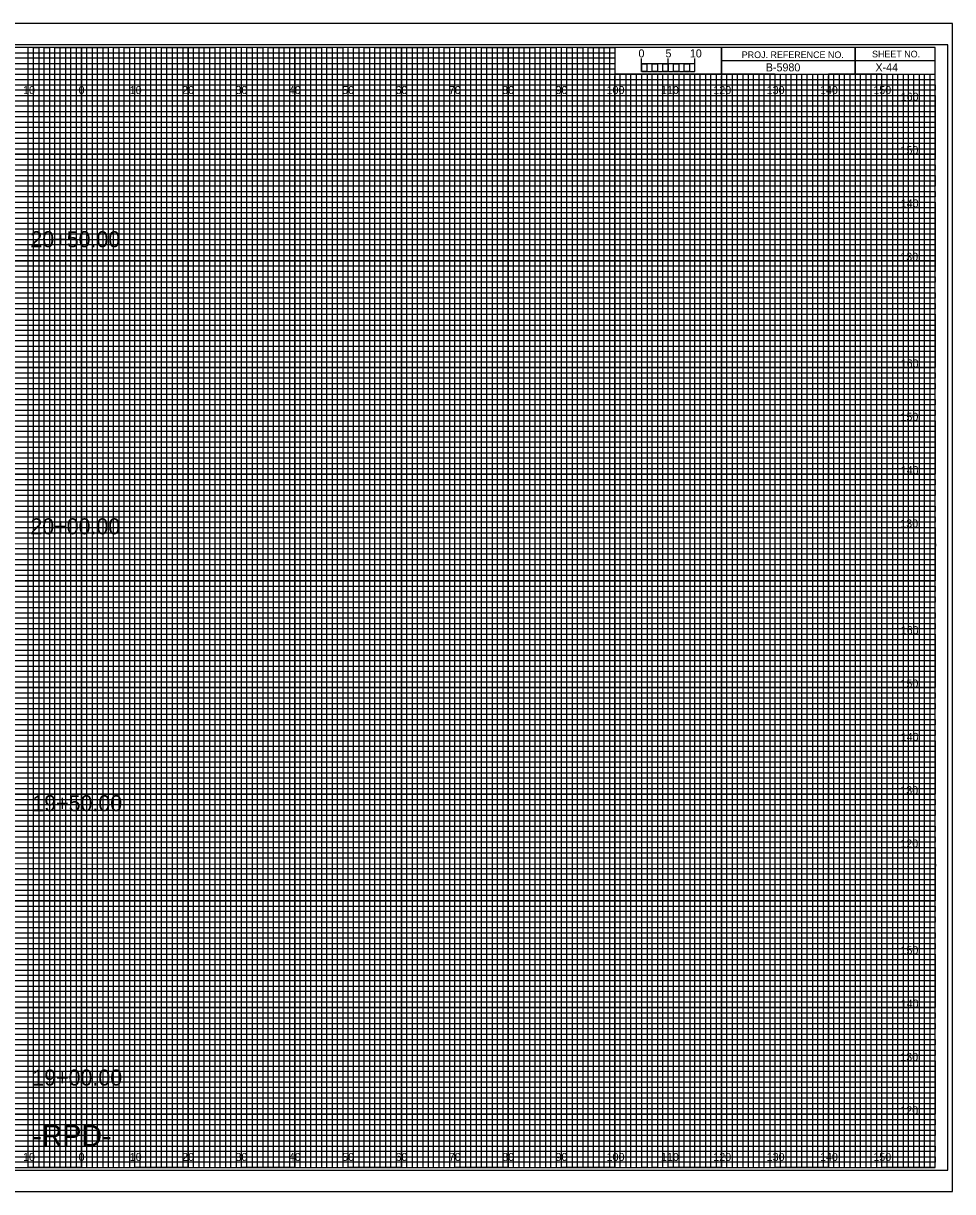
# Model space of a CAD drawing. Extents: x -13 to 323, y -5 to 874.
# Drawn here: x 149.1 to 323.3, y 435.5 to 654.5 of the extents above; entities that cross this region are included whole.
import ezdxf

# ---------------------------------------------------------------- set-up
doc = ezdxf.new("R2010")
doc.units = 0
for name, color, linetype in [('Exist Cross Section Cell', 7, 'Continuous'), ('Exist XS Center Line Elevation Label', 7, 'Continuous'), ('Exist XS Ground Line', 7, 'Continuous'), ('Prop CMT Conc Surface', 7, 'Continuous'), ('Prop CMT Concrete Structures', 7, 'Continuous'), ('Prop CMT Pvmt Course 1', 7, 'Continuous'), ('Prop CMT Pvmt Course 1 CG', 7, 'Continuous'), ('Prop CMT Pvmt Course 2', 7, 'Continuous'), ('Prop CMT Pvmt Course 3', 7, 'Continuous'), ('Prop CMT Pvmt Surface', 7, 'Continuous'), ('Prop CMT Pvmt Surface Shoulder', 7, 'Continuous'), ('Prop CMT Shld Paved Course 1', 7, 'Continuous'), ('Prop CMT Shld Paved Course 2', 7, 'Continuous'), ('Prop CMT Shld Paved Course 3', 7, 'Continuous'), ('Prop CMT Slope Grass', 7, 'Continuous'), ('Prop CMT Subgrade Earthwork', 7, 'Continuous'), ('Scratch_Level_1', 7, 'Continuous')]:
    doc.layers.add(name, color=color, linetype=linetype)

msp = doc.modelspace()

# ---------------------------------------------------------------- linework, layer by layer
at = {"layer": 'Exist XS Center Line Elevation Label'}
for points in [[(145, 440), (155, 440), (155, 650), (165, 650), (165, 440), (175, 440), (175, 650), (185, 650), (185, 440), (195, 440), (195, 650), (205, 650), (205, 440), (215, 440), (215, 650), (225, 650), (225, 440), (235, 440), (235, 650), (245, 650), (245, 440), (255, 440), (255, 650), (259.93, 650), (260, 650), (260, 645), (264.99, 645), (264.99, 440), (275, 440), (275, 645), (285, 645), (285, 440), (295, 440), (295, 645), (305, 645), (305, 440), (315, 440), (315, 645)], [(0, 645), (275, 645)], [(0, 625), (320, 625), (320, 635), (0, 635)], [(0, 605), (320, 605), (320, 615), (0, 615)], [(0, 585), (320, 585), (320, 595), (0, 595)], [(0, 565), (320, 565), (320, 575), (0, 575)], [(0, 545), (320, 545), (320, 555), (0, 555)], [(0, 525), (320, 525), (320, 535), (0, 535)], [(0, 505), (320, 505), (320, 515), (0, 515)], [(0, 485), (320, 485), (320, 495), (0, 495)], [(0, 465), (320, 465), (320, 475), (0, 475)], [(0, 445), (320, 445), (320, 455), (0, 455)]]:
    msp.add_lwpolyline(points, dxfattribs=at)
at = {"layer": 'Exist XS Ground Line'}
for p, q in [((150, 650), (140, 650)), ((150, 440), (150, 650)), ((170, 650), (160, 650)), ((160, 650), (160, 440)), ((170, 440), (170, 650)), ((190, 650), (180, 650)), ((180, 650), (180, 440)), ((190, 440), (190, 650)), ((210, 650), (200, 650)), ((200, 650), (200, 440)), ((210, 440), (210, 650)), ((230, 650), (220, 650)), ((220, 650), (220, 440)), ((230, 440), (230, 650)), ((250, 650), (240, 650)), ((240, 650), (240, 440)), ((250, 440), (250, 650)), ((260, 650), (260, 440)), ((270, 440), (270, 645)), ((290, 645), (280, 645)), ((280, 645), (280, 440)), ((290, 440), (290, 645)), ((310, 645), (300, 645)), ((300, 645), (300, 440)), ((310, 440), (310, 645)), ((160, 440), (150, 440)), ((180, 440), (170, 440)), ((200, 440), (190, 440)), ((220, 440), (210, 440)), ((240, 440), (230, 440)), ((260, 440), (250, 440)), ((280, 440), (270, 440)), ((300, 440), (290, 440)), ((320, 440), (310, 440)), ((320, 440), (320, 440))]:
    msp.add_line(p, q, dxfattribs=at)
for points in [[(0, 640), (320, 640), (320, 630), (0, 630)], [(0, 620), (320, 620), (320, 610), (0, 610)], [(0, 600), (320, 600), (320, 590), (0, 590)], [(0, 580), (320, 580), (320, 570), (0, 570)], [(0, 560), (320, 560), (320, 550), (0, 550)], [(0, 540), (320, 540), (320, 530), (0, 530)], [(0, 520), (320, 520), (320, 510), (0, 510)], [(0, 500), (320, 500), (320, 490), (0, 490)], [(0, 480), (320, 480), (320, 470), (0, 470)], [(0, 460), (320, 460), (320, 450), (0, 450)]]:
    msp.add_lwpolyline(points, dxfattribs=at)
at = {"layer": 'Prop CMT Pvmt Course 2'}
for p, q in [((265, 645.49), (265, 647.9)), ((265, 646.9), (265, 647.9)), ((270, 645.49), (270, 647.9)), ((275, 645.49), (275, 647.9)), ((275, 646.9), (275, 647.9))]:
    msp.add_line(p, q, dxfattribs=at)
for points in [[(275, 646.9), (265, 646.9), (265, 645.49), (275, 645.49)], [(265, 646.9), (266, 646.9), (266, 645.49), (265, 645.49)], [(267, 646.9), (268, 646.9), (268, 645.49), (267, 645.49)], [(269, 646.9), (270, 646.9), (270, 645.49), (269, 645.49)], [(271, 646.9), (272, 646.9), (272, 645.49), (271, 645.49)], [(273, 646.9), (274, 646.9), (274, 645.49), (273, 645.49)]]:
    msp.add_lwpolyline(points, close=True, dxfattribs=at)
at = {"layer": 'Prop CMT Pvmt Course 3'}
msp.add_lwpolyline([(-13.4, 435.5), (323.3, 435.5), (323.3, 654.5), (-13.4, 654.5)], close=True, dxfattribs=at)
at = {"layer": 'Prop CMT Pvmt Surface'}
for p, q in [((150, 440), (150, 650)), ((160, 440), (160, 650)), ((170, 440), (170, 650)), ((180, 440), (180, 650)), ((190, 440), (190, 650)), ((200, 440), (200, 650)), ((210, 440), (210, 650)), ((220, 440), (220, 650)), ((230, 440), (230, 650)), ((240, 440), (240, 650)), ((250, 440), (250, 650)), ((260, 440), (260, 644.69)), ((270, 440), (270, 644.69)), ((280, 440), (280, 644.69)), ((290, 440), (290, 644.69)), ((300, 440), (300, 644.69)), ((310, 440), (310, 644.69)), ((0, 640), (320, 640)), ((0, 630), (320, 630)), ((0, 620), (320, 620)), ((0, 610), (320, 610)), ((0, 600), (320, 600)), ((0, 590), (320, 590)), ((0, 580), (320, 580)), ((0, 570), (320, 570)), ((0, 560), (320, 560)), ((0, 550), (320, 550)), ((0, 540), (320, 540)), ((0, 530), (320, 530)), ((0, 520), (320, 520)), ((0, 510), (320, 510)), ((0, 500), (320, 500)), ((0, 490), (320, 490)), ((0, 480), (320, 480)), ((0, 470), (320, 470)), ((0, 460), (320, 460)), ((0, 450), (320, 450))]:
    msp.add_line(p, q, dxfattribs=at)
at = {"layer": 'Prop CMT Pvmt Surface Shoulder'}
for p, q in [((323.3, 654.5), (-13.4, 654.5)), ((-13.4, 435.5), (323.3, 435.5))]:
    msp.add_line(p, q, dxfattribs=at)
at = {"layer": 'Prop CMT Shld Paved Course 1'}
for p, q in [((0, 649), (260, 649)), ((260, 649), (260, 647.98)), ((260, 647.98), (0, 647.98)), ((0, 647), (260, 647)), ((260, 647), (260, 645.89)), ((260, 645.89), (0, 645.89)), ((0, 644), (320, 644))]:
    msp.add_line(p, q, dxfattribs=at)
for points in [[(0, 643), (270, 643), (320, 643), (320, 642), (0, 642)], [(0, 641), (320, 641), (320, 639), (0, 639)], [(0, 638), (320, 638), (320, 637), (0, 636.98)], [(0, 636), (320, 636), (320, 634), (0, 634)], [(0, 633), (320, 633), (320, 632), (0, 632)], [(0, 631), (320, 631), (320, 629), (0, 629)], [(0, 628), (320, 628), (320, 627), (0, 627)], [(0, 626), (320, 626), (320, 624), (0, 624)], [(0, 623), (320, 623), (320, 622), (0, 622)], [(0, 621), (320, 621), (320, 619), (0, 619)], [(0, 618), (320, 618), (320, 617), (0, 617)], [(0, 616), (320, 616), (320, 613.95), (320, 613), (320, 612), (0, 612)], [(0, 614), (320, 614), (320, 613), (0, 613)], [(0, 611), (320, 611), (320, 609), (0, 609.03)], [(0, 609.03), (320, 609), (320, 608), (0, 608)], [(0, 607), (320, 607), (320, 606), (0, 606)], [(0, 604), (320, 604), (320, 603), (0, 603)], [(0, 602), (320, 602), (320, 601), (0, 601)], [(-0.07, 598.89), (320, 598.89), (320, 597.88), (-0.07, 597.88)], [(0, 597), (320, 597), (320, 596), (0, 596)], [(0, 594), (320, 594), (320, 593), (0, 593)], [(0, 592), (320, 592), (320, 591), (0, 591)], [(0, 589), (320, 589), (320, 588), (0, 588)], [(0, 587), (320, 587), (320, 586), (0, 586)], [(0, 584), (320, 584), (320, 583), (0, 583)], [(0, 582), (320, 582), (320, 581), (0, 581)], [(0, 579), (320, 579), (319.99, 577.98), (0, 578)], [(0, 577), (320, 577), (320, 576), (0, 576)], [(0, 574), (320, 574), (320, 573), (0, 573)], [(0, 572), (320, 572), (320, 571), (0, 571)], [(0, 569), (320, 569), (320, 568), (0, 568)], [(0, 567), (320, 567), (320, 566), (0, 566)], [(0, 564), (320, 564), (320, 563), (0, 563)], [(0, 562), (320, 562), (320, 561), (0, 561)], [(0, 559), (320, 559), (320, 558), (0, 558)], [(0, 556.99), (320.07, 556.91), (320, 556), (0, 556)], [(0, 554), (320, 554), (320, 553), (0, 553)], [(0, 552), (320, 552), (320, 551), (0, 551)], [(0, 549), (320, 549), (320, 548), (0, 548)], [(0, 547), (320, 547), (320, 546), (0, 546)], [(0, 544), (320, 544), (320, 543), (0, 543)], [(0, 542), (320, 542), (320, 541), (0, 541)], [(0, 539), (320, 539), (320, 538), (0, 538)], [(0, 537), (320, 537), (320, 536), (0, 536)], [(0, 534), (320, 534), (320, 533), (0, 533)], [(0, 532), (320, 532), (320, 531), (0, 531)], [(0, 529), (320, 529), (320, 528), (0, 528)], [(0, 527), (320, 527), (320, 526), (0, 526)], [(0, 524), (320, 524), (320, 523), (0, 523)], [(0, 522), (320, 522), (320, 521), (0, 521)], [(0, 519), (320, 519), (319.99, 517.98), (0, 518)], [(0, 517), (320, 517), (320, 516), (0, 516)], [(0, 514), (320, 514), (320, 513), (0, 513)], [(0, 512), (320, 512), (320, 511), (0, 511)], [(0, 509), (320, 509), (320, 508), (0, 508)], [(0, 507), (320, 507), (320, 506), (0, 506)], [(0, 504), (320, 504), (320, 503), (0, 503)], [(0, 502), (320, 502), (320, 501), (0, 501)], [(0, 499), (320, 499), (320, 498), (0, 498)], [(0, 496.99), (320.07, 496.91), (320, 496), (0, 496)], [(0, 494), (320, 494), (320, 493), (0, 493)], [(0, 492), (320, 492), (320, 491), (0, 491)], [(0, 489), (320, 489), (320, 488), (0, 488)], [(0, 487), (320, 487), (320, 486), (0, 486)], [(0, 484), (320, 484), (320, 483), (0, 483)], [(0, 482), (320, 482), (320, 481), (0, 481)], [(0, 479), (320, 479), (320, 478), (0, 478)], [(0, 477), (320, 477), (320, 476), (0, 476)], [(0, 474), (320, 474), (320, 473), (0, 473)], [(0, 472), (320, 472), (320, 471), (0, 471)], [(0, 469), (320, 469), (320, 468), (0, 468)], [(0, 467), (320, 467), (320, 466), (0, 466)], [(0, 464), (320, 464), (320, 463), (0, 463)], [(0, 462), (320, 462), (320, 461), (0, 461)], [(0, 459), (320, 459), (320, 458), (0, 458)], [(0, 457), (320, 457), (320, 456), (0, 456)], [(0, 454), (320, 454), (320, 453), (0, 453)], [(0, 452), (320, 452), (320, 451), (0, 451)], [(0, 449), (320, 449), (320, 448), (0, 448)], [(0, 447), (320, 447), (320, 446), (0, 446)], [(0, 444), (320, 444), (320, 443), (0, 443)], [(0, 442), (320, 442), (320, 441), (0, 441)]]:
    msp.add_lwpolyline(points, dxfattribs=at)
at = {"layer": 'Prop CMT Shld Paved Course 2'}
for p, q in [((305, 650), (305, 645)), ((305, 645), (305, 650)), ((280, 647.5), (280, 645)), ((320, 647.49), (280, 647.49)), ((280, 645), (320, 645))]:
    msp.add_line(p, q, dxfattribs=at)
for points in [[(320, 650), (0, 650), (0, 440), (320, 440)], [(280, 650), (260, 650), (260, 645.03), (280, 645.03)], [(320, 650), (280, 650), (280, 645), (320, 645)]]:
    msp.add_lwpolyline(points, close=True, dxfattribs=at)
at = {"layer": 'Prop CMT Shld Paved Course 3'}
for p, q in [((267, 645), (266.01, 645)), ((266.01, 645), (266.01, 440)), ((267, 440), (267, 645)), ((269, 645), (268, 645)), ((268, 645), (268, 440)), ((269, 440), (269, 645)), ((266.01, 440), (265, 440)), ((268, 440), (267, 440))]:
    msp.add_line(p, q, dxfattribs=at)
for points in [[(150, 440), (151, 440), (151, 650), (152, 650), (152, 440)], [(152, 440), (153, 440), (153, 650), (154, 650), (154, 440)], [(155, 440), (156, 440), (156, 650), (157, 650), (157, 440)], [(157, 440), (158, 440), (158, 650), (159, 650), (159, 440)], [(160, 440), (161, 440), (161, 650), (162, 650), (162, 440)], [(162, 440), (163, 440), (163, 650), (164, 650), (164, 440)], [(165, 440), (166, 440), (166, 650), (167, 650), (167, 440)], [(167, 440), (168, 440), (168, 650), (169, 650), (169, 440)], [(170, 440), (171, 440), (171, 650), (172, 650), (172, 440)], [(172, 440), (173, 440), (173, 650), (174, 650), (174, 440)], [(175, 440), (176, 440), (176, 650), (177, 650), (177, 440)], [(177, 440), (178, 440), (178, 650), (179, 650), (179, 440)], [(180, 440), (181, 440), (181, 650), (182, 650), (182, 440)], [(182, 440), (183, 440), (183, 650), (184, 650), (184, 440)], [(185, 440), (186, 440), (186, 650), (187, 650), (187, 440)], [(187, 440), (188, 440), (188, 650), (189, 650), (189, 440)], [(190, 440), (191, 440), (191, 650), (192, 650), (192, 440)], [(192, 440), (193, 440), (193, 650), (194, 650), (194, 440)], [(195, 440), (196, 440), (196, 650), (197, 650), (197, 440)], [(197, 440), (198, 440), (198, 650), (199, 650), (199, 440)], [(200, 440), (201, 440), (201, 650), (202, 650), (202, 440)], [(202, 440), (203, 440), (203, 650), (204, 650), (204, 440)], [(205, 440), (206, 440), (206, 650), (207, 650), (207, 440)], [(207, 440), (208, 440), (208, 650), (209, 650), (209, 440)], [(210, 440), (211, 440), (211, 650), (212, 650), (212, 440)], [(212, 440), (213, 440), (213, 650), (214, 650), (214, 440)], [(215, 440), (216, 440), (216, 650), (217, 650), (217, 440)], [(217, 440), (218, 440), (218, 650), (219, 650), (219, 440)], [(220, 440), (221, 440), (221, 650), (222, 650), (222, 440)], [(222, 440), (223, 440), (223, 650), (224, 650), (224, 440)], [(225, 440), (226, 440), (226, 650), (227, 650), (227, 440)], [(227, 440), (228, 440), (228, 650), (229, 650), (229, 440)], [(230, 440), (231, 440), (231, 650), (232, 650), (232, 440)], [(232, 440), (233, 440), (233, 650), (234, 650), (234, 440)], [(235, 440), (236, 440), (236, 650), (237, 650), (237, 440)], [(237, 440), (238, 440), (238, 650), (239, 650), (239, 440)], [(240, 440), (241, 440), (241, 650), (242, 650), (242, 440)], [(242, 440), (243, 440), (243, 650), (244, 650), (244, 440)], [(245, 440), (246, 440), (246, 650), (247, 650), (247, 440)], [(247, 440), (248, 440), (248, 650), (249, 650), (249, 440)], [(250, 440), (251, 440), (251, 650), (252, 650), (252, 440)], [(252, 440), (253, 440), (253, 650), (254, 650), (254, 440)], [(255, 440), (256, 440), (256, 650), (257, 650), (257, 440)], [(257, 440), (258, 440), (258, 650), (259, 650), (259, 440)], [(260, 440), (261, 440), (261, 645), (262.02, 645), (262.02, 440)], [(262, 440), (263, 440), (263, 645), (263.99, 645), (263.99, 440)], [(270, 440), (270.98, 440), (270.98, 645), (272, 645), (272, 440)], [(272, 440), (273, 440), (273, 645), (274.05, 645), (274.05, 440)], [(275, 440), (276, 440), (276, 645), (277, 645), (277, 440)], [(277, 440), (278, 440), (278, 645), (279, 645), (279, 440)], [(280, 440), (281, 440), (281, 645), (282, 645), (282, 440)], [(282, 440), (283, 440), (283, 645), (284, 645), (284, 440)], [(285, 440), (286, 440), (286, 645), (287, 645), (287, 440)], [(287, 440), (288, 440), (288, 645), (289, 645), (289, 440)], [(290, 440), (291, 440), (291, 645), (292, 645), (292, 440)], [(292, 440), (293, 440), (293, 645), (294, 645), (294, 440)], [(295, 440), (296, 440), (296, 645), (297, 645), (297, 440)], [(297, 440), (298, 440), (298, 645), (299, 645), (299, 440)], [(300, 440), (301, 440), (301, 645), (302, 645), (302, 440)], [(302, 440), (303, 440), (303, 645), (304, 645), (304, 440)], [(305, 440), (306, 440), (306, 645), (307, 645), (307, 440)], [(307, 440), (308, 440), (308, 645), (309, 645), (309, 440)], [(310, 440), (311, 440), (311, 645), (312, 645), (312, 440)], [(312, 440), (313, 440), (313, 645), (314, 645), (314, 440)], [(315, 440), (316, 440), (316, 645), (317, 645), (317, 440)], [(317, 440), (318, 440), (318, 645), (319, 645), (319, 440)]]:
    msp.add_lwpolyline(points, dxfattribs=at)
at = {"layer": 'Prop CMT Subgrade Earthwork'}
msp.add_lwpolyline([(-10.8, 439.5), (322.4, 439.5), (322.4, 650.5), (-10.8, 650.5)], close=True, dxfattribs=at)

# ---------------------------------------------------------------- texts
at = {"layer": 'Exist Cross Section Cell'}
for s, p in [('10', (149.04, 641.25)), ('0', (159.45, 641.25)), ('0', (159.45, 641.25)), ('10', (169.04, 641.25)), ('20', (178.86, 641.25)), ('30', (188.86, 641.25)), ('40', (198.86, 641.25)), ('50', (208.86, 641.25)), ('60', (218.86, 641.25)), ('70', (228.86, 641.25)), ('80', (238.86, 641.25)), ('90', (248.86, 641.25)), ('100', (258.44, 641.25)), ('110', (268.62, 641.25)), ('120', (278.44, 641.25)), ('130', (288.44, 641.25)), ('140', (298.44, 641.25)), ('150', (308.44, 641.25)), ('10', (149.04, 441.25)), ('0', (159.45, 441.25)), ('0', (159.45, 441.25)), ('10', (169.04, 441.25)), ('20', (178.86, 441.25)), ('30', (188.86, 441.25)), ('40', (198.86, 441.25)), ('50', (208.86, 441.25)), ('60', (218.86, 441.25)), ('70', (228.86, 441.25)), ('80', (238.86, 441.25)), ('90', (248.86, 441.25)), ('100', (258.44, 441.25)), ('110', (268.62, 441.25)), ('120', (278.44, 441.25)), ('130', (288.44, 441.25)), ('140', (298.44, 441.25)), ('150', (308.44, 441.25))]:
    msp.add_text(s, height=1.5, dxfattribs=at).set_placement(p)
at = {"layer": 'Prop CMT Conc Surface'}
for s, p in [('5', (269.47, 648.12)), ('10', (274.04, 648.12))]:
    msp.add_text(s, height=1.5, dxfattribs=at).set_placement(p)
at = {"layer": 'Prop CMT Concrete Structures'}
msp.add_text('B-5980', height=1.5, dxfattribs=at).set_placement((288.28, 645.5))
at = {"layer": 'Prop CMT Pvmt Course 1'}
for s, p in [('160', (313.57, 640)), ('150', (313.52, 630)), ('140', (313.57, 620)), ('130', (313.49, 610)), ('160', (313.57, 590)), ('150', (313.52, 580)), ('140', (313.57, 570)), ('130', (313.49, 560)), ('160', (313.57, 540)), ('150', (313.52, 530)), ('140', (313.57, 520)), ('130', (313.49, 510)), ('120', (313.5, 500)), ('150', (313.52, 480)), ('140', (313.57, 470)), ('130', (313.49, 460)), ('120', (313.5, 450))]:
    msp.add_text(s, height=1.5, dxfattribs=at).set_placement(p)
at = {"layer": 'Prop CMT Pvmt Course 1 CG'}
msp.add_text('-RPD-', height=4, dxfattribs=at).set_placement((150.78, 444))
at = {"layer": 'Prop CMT Pvmt Course 2'}
msp.add_text('0', height=1.5, dxfattribs=at).set_placement((264.41, 648.12))
at = {"layer": 'Prop CMT Shld Paved Course 2'}
for s, p in [('PROJ. REFERENCE NO.', (283.77, 647.99)), ('SHEET NO.', (308.19, 648.12))]:
    msp.add_text(s, height=1.25, dxfattribs=at).set_placement(p)
at = {"layer": 'Prop CMT Slope Grass'}
for s, p in [('20+50.00', (150.41, 612.54)), ('20+00.00', (150.41, 558.72)), ('19+50.00', (150.77, 506.82)), ('19+00.00', (150.77, 455.39))]:
    msp.add_text(s, height=3, dxfattribs=at).set_placement(p)
at = {"layer": 'Scratch_Level_1'}
msp.add_text('X-44', height=1.5, dxfattribs=at).set_placement((308.83, 645.5))

doc.saveas('drawing.dxf')
